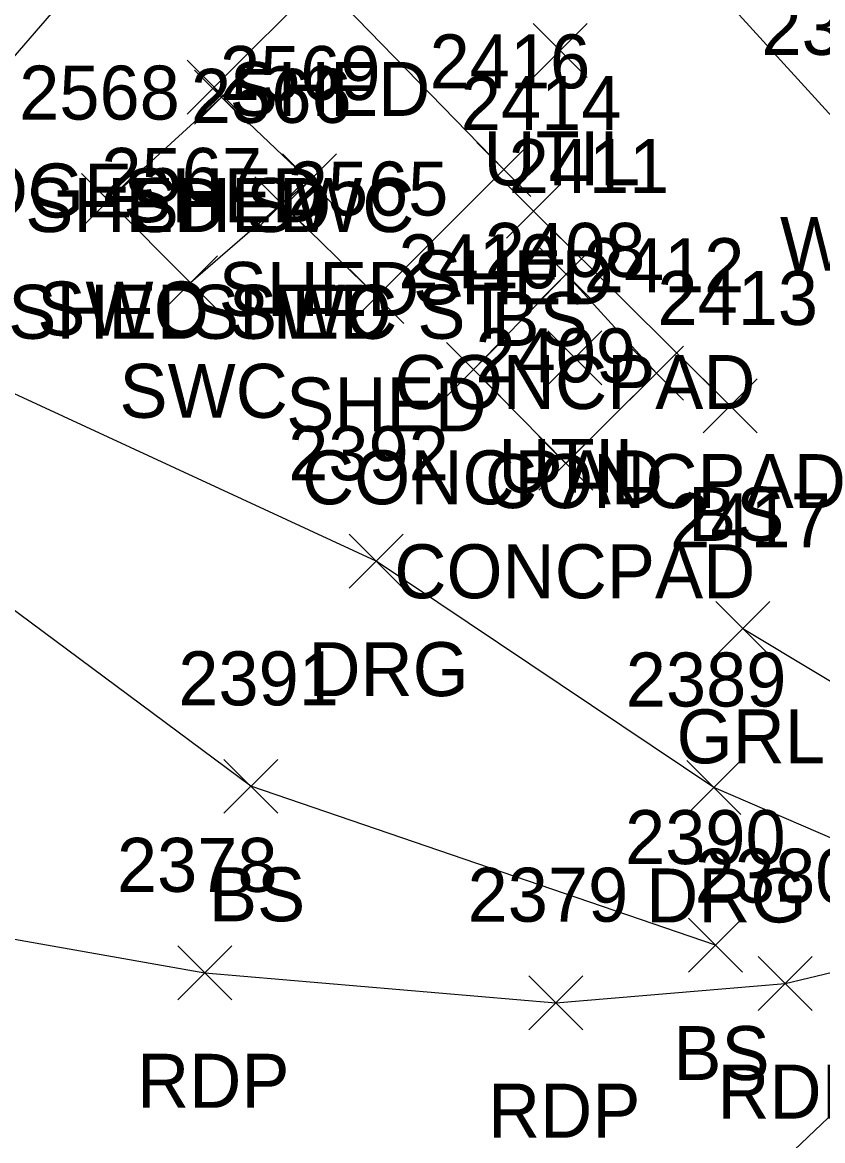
# Model space of a CAD drawing. Extents: x 1653135 to 1655489, y 602711 to 605684.
# Drawn here: x 1653689.27 to 1653718.91, y 605260.26 to 605301.69 of the extents above; entities that cross this region are included whole.
import ezdxf

# ---------------------------------------------------------------- set-up
doc = ezdxf.new("R2010")
doc.units = 0
for name, color, linetype in [('L_A', 7, 'Continuous'), ('L_I', 7, 'Continuous'), ('L_TIC', 7, 'Continuous'), ('LAHR', 7, 'Continuous'), ('LAWA', 7, 'Continuous'), ('LBC', 7, 'Continuous'), ('LELB', 7, 'Continuous'), ('LS', 7, 'Continuous'), ('P_A', 7, 'Continuous'), ('P_I', 7, 'Continuous'), ('P_TIC', 7, 'Continuous'), ('PET', 7, 'Continuous'), ('PRC', 7, 'Continuous'), ('R_A', 7, 'Continuous'), ('R_I', 7, 'Continuous'), ('R_TIC', 7, 'Continuous'), ('RDG', 7, 'Continuous'), ('RGR', 7, 'Continuous'), ('RSW', 7, 'Continuous'), ('U_A', 7, 'Continuous'), ('U_I', 7, 'Continuous'), ('UDEFAULT', 7, 'Continuous')]:
    doc.layers.add(name, color=color, linetype=linetype)

msp = doc.modelspace()

# ---------------------------------------------------------------- linework, layer by layer
at = {"layer": 'L_TIC'}
for points in [[(1653695.373, 605298.283), (1653697.373, 605300.283)], [(1653697.373, 605298.283), (1653695.373, 605300.283)], [(1653695.373, 605298.283), (1653697.373, 605300.283)], [(1653697.373, 605298.283), (1653695.373, 605300.283)], [(1653695.643, 605297.919), (1653697.643, 605299.919)], [(1653697.643, 605297.919), (1653695.643, 605299.919)], [(1653695.643, 605297.919), (1653697.643, 605299.919)], [(1653697.643, 605297.919), (1653695.643, 605299.919)], [(1653706.103, 605295.241), (1653708.103, 605297.241)], [(1653708.103, 605295.241), (1653706.103, 605297.241)], [(1653706.103, 605295.241), (1653708.103, 605297.241)], [(1653708.103, 605295.241), (1653706.103, 605297.241)], [(1653698.902, 605294.811), (1653700.902, 605296.811)], [(1653700.902, 605294.811), (1653698.902, 605296.811)], [(1653698.902, 605294.811), (1653700.902, 605296.811)], [(1653700.902, 605294.811), (1653698.902, 605296.811)], [(1653697.876, 605293.964), (1653699.876, 605295.964)], [(1653699.876, 605293.964), (1653697.876, 605295.964)], [(1653697.876, 605293.964), (1653699.876, 605295.964)], [(1653699.876, 605293.964), (1653697.876, 605295.964)], [(1653707.202, 605293.698), (1653709.202, 605295.698)], [(1653709.202, 605293.698), (1653707.202, 605295.698)], [(1653707.202, 605293.698), (1653709.202, 605295.698)], [(1653709.202, 605293.698), (1653707.202, 605295.698)], [(1653708.409, 605291.361), (1653710.409, 605293.361)], [(1653710.409, 605291.361), (1653708.409, 605293.361)], [(1653708.409, 605291.361), (1653710.409, 605293.361)], [(1653710.409, 605291.361), (1653708.409, 605293.361)], [(1653701.404, 605290.53), (1653703.404, 605292.53)], [(1653703.404, 605290.53), (1653701.404, 605292.53)], [(1653701.404, 605290.53), (1653703.404, 605292.53)], [(1653703.404, 605290.53), (1653701.404, 605292.53)], [(1653704.982, 605287.832), (1653706.982, 605289.832)], [(1653706.982, 605287.832), (1653704.982, 605289.832)], [(1653704.982, 605287.832), (1653706.982, 605289.832)], [(1653706.982, 605287.832), (1653704.982, 605289.832)], [(1653711.758, 605287.691), (1653713.758, 605289.691)], [(1653713.758, 605287.691), (1653711.758, 605289.691)], [(1653711.758, 605287.691), (1653713.758, 605289.691)], [(1653713.758, 605287.691), (1653711.758, 605289.691)], [(1653714.487, 605286.476), (1653716.487, 605288.476)], [(1653716.487, 605286.476), (1653714.487, 605288.476)], [(1653714.487, 605286.476), (1653716.487, 605288.476)], [(1653716.487, 605286.476), (1653714.487, 605288.476)], [(1653708.401, 605284.35), (1653710.401, 605286.35)], [(1653710.401, 605284.35), (1653708.401, 605286.35)], [(1653708.401, 605284.35), (1653710.401, 605286.35)], [(1653710.401, 605284.35), (1653708.401, 605286.35)], [(1653696.737, 605272.383), (1653698.737, 605274.383)], [(1653698.737, 605272.383), (1653696.737, 605274.383)], [(1653696.737, 605272.383), (1653698.737, 605274.383)], [(1653698.737, 605272.383), (1653696.737, 605274.383)], [(1653713.941, 605266.501), (1653715.941, 605268.501)], [(1653715.941, 605266.501), (1653713.941, 605268.501)], [(1653713.941, 605266.501), (1653715.941, 605268.501)], [(1653715.941, 605266.501), (1653713.941, 605268.501)]]:
    msp.add_lwpolyline(points, dxfattribs=at)
at = {"layer": 'LAHR'}
msp.add_lwpolyline([(1653688.126, 605299.458), (1653695.956, 605308.517)], dxfattribs=at)
at = {"layer": 'LAWA'}
msp.add_lwpolyline([(1653692.976, 605320.073), (1653709.42, 605308.994), (1653719.916, 605297.482), (1653727.245, 605289.031)], dxfattribs=at)
at = {"layer": 'LBC'}
for points in [[(1653700.31, 605303.223), (1653707.103, 605296.241), (1653702.404, 605291.53), (1653698.876, 605294.964), (1653699.902, 605295.811), (1653696.643, 605298.919), (1653696.373, 605299.283)], [(1653696.373, 605299.283), (1653700.31, 605303.223)]]:
    msp.add_lwpolyline(points, dxfattribs=at)
at = {"layer": 'LELB'}
for points in [[(1653714.941, 605267.501), (1653697.737, 605273.383), (1653667.38, 605295.938)], [(1653715.487, 605287.476), (1653708.202, 605294.698)]]:
    msp.add_lwpolyline(points, dxfattribs=at)
at = {"layer": 'LS'}
for points in [[(1653709.401, 605285.35), (1653705.982, 605288.832), (1653709.409, 605292.361), (1653712.758, 605288.691)], [(1653712.758, 605288.691), (1653709.401, 605285.35)]]:
    msp.add_lwpolyline(points, dxfattribs=at)
at = {"layer": 'P_TIC'}
for points in [[(1653695.029, 605265.473), (1653697.029, 605267.473)], [(1653697.029, 605265.473), (1653695.029, 605267.473)], [(1653695.029, 605265.473), (1653697.029, 605267.473)], [(1653697.029, 605265.473), (1653695.029, 605267.473)], [(1653716.526, 605265.073), (1653718.526, 605267.073)], [(1653718.526, 605265.073), (1653716.526, 605267.073)], [(1653716.526, 605265.073), (1653718.526, 605267.073)], [(1653718.526, 605265.073), (1653716.526, 605267.073)], [(1653708.03, 605264.366), (1653710.03, 605266.366)], [(1653710.03, 605264.366), (1653708.03, 605266.366)], [(1653708.03, 605264.366), (1653710.03, 605266.366)], [(1653710.03, 605264.366), (1653708.03, 605266.366)]]:
    msp.add_lwpolyline(points, dxfattribs=at)
at = {"layer": 'PET'}
msp.add_lwpolyline([(1653654.524, 605279.776), (1653665.481, 605274.477), (1653678.068, 605269.653), (1653696.029, 605266.473), (1653709.03, 605265.366), (1653717.526, 605266.073), (1653726.648, 605268.269), (1653743.088, 605277.115), (1653755.463, 605259.253), (1653765.921, 605244.563), (1653757.558, 605236.881), (1653747.498, 605222.75), (1653729.711, 605207.167), (1653718.29, 605197.382), (1653709.642, 605189.343), (1653699.377, 605174.783), (1653695.369, 605174.396), (1653690.143, 605165.647), (1653683.772, 605149.176), (1653674.351, 605119.826), (1653662.023, 605081.754)], dxfattribs=at)
at = {"layer": 'PRC'}
msp.add_lwpolyline([(1653726.648, 605268.269), (1653711.087, 605253.466), (1653692.662, 605235.598), (1653674.715, 605225.537), (1653647.978, 605202.943)], dxfattribs=at)
at = {"layer": 'R_TIC'}
for points in [[(1653695.643, 605297.919), (1653697.643, 605299.919)], [(1653697.643, 605297.919), (1653695.643, 605299.919)], [(1653695.643, 605297.919), (1653697.643, 605299.919)], [(1653697.643, 605297.919), (1653695.643, 605299.919)], [(1653691.457, 605294.085), (1653693.457, 605296.085)], [(1653693.457, 605294.085), (1653691.457, 605296.085)], [(1653691.457, 605294.085), (1653693.457, 605296.085)], [(1653693.457, 605294.085), (1653691.457, 605296.085)], [(1653697.876, 605293.964), (1653699.876, 605295.964)], [(1653699.876, 605293.964), (1653697.876, 605295.964)], [(1653697.876, 605293.964), (1653699.876, 605295.964)], [(1653699.876, 605293.964), (1653697.876, 605295.964)], [(1653694.501, 605291.036), (1653696.501, 605293.036)], [(1653696.501, 605291.036), (1653694.501, 605293.036)], [(1653694.501, 605291.036), (1653696.501, 605293.036)], [(1653696.501, 605291.036), (1653694.501, 605293.036)], [(1653701.376, 605280.724), (1653703.376, 605282.724)], [(1653703.376, 605280.724), (1653701.376, 605282.724)], [(1653701.376, 605280.724), (1653703.376, 605282.724)], [(1653703.376, 605280.724), (1653701.376, 605282.724)], [(1653714.96, 605278.234), (1653716.96, 605280.234)], [(1653716.96, 605278.234), (1653714.96, 605280.234)], [(1653714.96, 605278.234), (1653716.96, 605280.234)], [(1653716.96, 605278.234), (1653714.96, 605280.234)], [(1653713.889, 605272.34), (1653715.889, 605274.34)], [(1653715.889, 605272.34), (1653713.889, 605274.34)], [(1653713.889, 605272.34), (1653715.889, 605274.34)], [(1653715.889, 605272.34), (1653713.889, 605274.34)]]:
    msp.add_lwpolyline(points, dxfattribs=at)
at = {"layer": 'RDG'}
for points in [[(1653702.376, 605281.724), (1653675.729, 605294.055)], [(1653726.648, 605268.269), (1653714.889, 605273.34), (1653702.376, 605281.724)]]:
    msp.add_lwpolyline(points, dxfattribs=at)
at = {"layer": 'RGR'}
msp.add_lwpolyline([(1653715.96, 605279.234), (1653721.533, 605275.88), (1653727.394, 605274.891), (1653741.217, 605277.707)], dxfattribs=at)
at = {"layer": 'RSW'}
msp.add_lwpolyline([(1653698.876, 605294.964), (1653695.501, 605292.036), (1653692.457, 605295.085), (1653696.643, 605298.919)], dxfattribs=at)
at = {"layer": 'UDEFAULT'}
for points in [[(1653708.186, 605299.649), (1653710.186, 605301.649)], [(1653710.186, 605299.649), (1653708.186, 605301.649)], [(1653708.735, 605288.257), (1653710.735, 605290.257)], [(1653710.735, 605288.257), (1653708.735, 605290.257)]]:
    msp.add_lwpolyline(points, dxfattribs=at)

# ---------------------------------------------------------------- texts
at = {"layer": 'L_A'}
for s, p in [('SHED', (1653696.948, 605298.223)), ('SHED', (1653696.948, 605298.223)), ('HEDGE', (1653683.827, 605294.458)), ('HEDGE', (1653683.827, 605294.458)), ('SHED', (1653693.011, 605294.283)), ('SHED', (1653693.011, 605294.283)), ('SHED', (1653693.28, 605293.919)), ('SHED', (1653693.28, 605293.919)), ('WDL', (1653717.333, 605292.482)), ('WDL', (1653717.333, 605292.482)), ('SHED', (1653703.741, 605291.241)), ('SHED', (1653703.741, 605291.241)), ('SHED', (1653696.54, 605290.811)), ('SHED', (1653696.54, 605290.811)), ('SHED', (1653695.514, 605289.964)), ('SHED', (1653695.514, 605289.964)), ('BS', (1653706.643, 605289.698)), ('BS', (1653706.643, 605289.698)), ('CONCPAD', (1653703.054, 605287.361)), ('CONCPAD', (1653703.054, 605287.361)), ('SHED', (1653699.041, 605286.53)), ('SHED', (1653699.041, 605286.53)), ('CONCPAD', (1653699.627, 605283.832)), ('CONCPAD', (1653699.627, 605283.832)), ('CONCPAD', (1653706.404, 605283.691)), ('CONCPAD', (1653706.404, 605283.691)), ('BS', (1653713.928, 605282.476)), ('BS', (1653713.928, 605282.476)), ('CONCPAD', (1653703.046, 605280.35)), ('CONCPAD', (1653703.046, 605280.35)), ('BS', (1653696.178, 605268.383)), ('BS', (1653696.178, 605268.383)), ('BS', (1653713.382, 605262.501)), ('BS', (1653713.382, 605262.501))]:
    msp.add_text(s, height=2, dxfattribs=at).set_placement(p)
at = {"layer": 'L_I'}
for s, p in [('2399', (1653716.648, 605300.482)), ('2399', (1653716.648, 605300.482)), ('2416', (1653704.355, 605299.241)), ('2416', (1653704.355, 605299.241)), ('2569', (1653696.587, 605298.811)), ('2569', (1653696.587, 605298.811)), ('2566', (1653695.514, 605297.964)), ('2566', (1653695.514, 605297.964)), ('2414', (1653705.509, 605297.698)), ('2414', (1653705.509, 605297.698)), ('2411', (1653707.283, 605295.361)), ('2411', (1653707.283, 605295.361)), ('2565', (1653699.097, 605294.53)), ('2565', (1653699.097, 605294.53)), ('2410', (1653703.202, 605291.832)), ('2410', (1653703.202, 605291.832)), ('2412', (1653710.065, 605291.691)), ('2412', (1653710.065, 605291.691)), ('2413', (1653712.794, 605290.476)), ('2413', (1653712.794, 605290.476)), ('2409', (1653706.054, 605288.35)), ('2409', (1653706.054, 605288.35)), ('2391', (1653695.044, 605276.383)), ('2391', (1653695.044, 605276.383)), ('2390', (1653711.595, 605270.501)), ('2390', (1653711.595, 605270.501))]:
    msp.add_text(s, height=2, dxfattribs=at).set_placement(p)
at = {"layer": 'P_A'}
for p in [(1653693.517, 605261.473), (1653693.517, 605261.473), (1653715.014, 605261.073), (1653715.014, 605261.073), (1653706.518, 605260.366), (1653706.518, 605260.366)]:
    msp.add_text('RDP', height=2, dxfattribs=at).set_placement(p)
at = {"layer": 'P_I'}
for s, p in [('2378', (1653692.77, 605269.473)), ('2378', (1653692.77, 605269.473)), ('2380', (1653714.18, 605269.073)), ('2380', (1653714.18, 605269.073)), ('2379', (1653705.762, 605268.366)), ('2379', (1653705.762, 605268.366))]:
    msp.add_text(s, height=2, dxfattribs=at).set_placement(p)
at = {"layer": 'R_A'}
for s, p in [('SHED SWC', (1653689.375, 605293.919)), ('SHED SWC', (1653689.375, 605293.919)), ('SHED SWC ST', (1653688.743, 605289.964)), ('SHED SWC ST', (1653688.743, 605289.964)), ('SWC', (1653689.819, 605290.085)), ('SWC', (1653689.819, 605290.085)), ('SWC', (1653692.863, 605287.036)), ('SWC', (1653692.863, 605287.036)), ('DRG', (1653699.864, 605276.724)), ('DRG', (1653699.864, 605276.724)), ('GRL', (1653713.503, 605274.234)), ('GRL', (1653713.503, 605274.234)), ('DRG', (1653712.377, 605268.34)), ('DRG', (1653712.377, 605268.34))]:
    msp.add_text(s, height=2, dxfattribs=at).set_placement(p)
at = {"layer": 'R_I'}
for s, p in [('2568', (1653689.15, 605298.085)), ('2568', (1653689.15, 605298.085)), ('2566', (1653695.514, 605297.964)), ('2566', (1653695.514, 605297.964)), ('2567', (1653692.194, 605295.036)), ('2567', (1653692.194, 605295.036)), ('2392', (1653699.116, 605284.724)), ('2392', (1653699.116, 605284.724)), ('2417', (1653713.267, 605282.234)), ('2417', (1653713.267, 605282.234)), ('2389', (1653711.622, 605276.34)), ('2389', (1653711.622, 605276.34))]:
    msp.add_text(s, height=2, dxfattribs=at).set_placement(p)
at = {"layer": 'U_A'}
for p in [(1653706.352, 605295.649), (1653706.9, 605284.257)]:
    msp.add_text('UTIL', height=2, dxfattribs=at).set_placement(p)
at = {"layer": 'U_I'}
msp.add_text('2408', height=2, dxfattribs=at).set_placement((1653706.396, 605292.257))

doc.saveas('drawing.dxf')
